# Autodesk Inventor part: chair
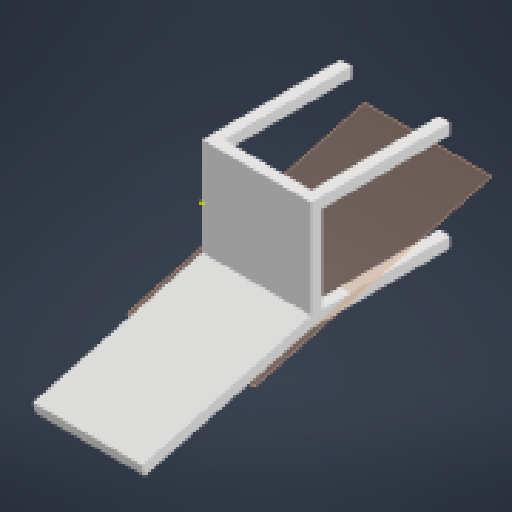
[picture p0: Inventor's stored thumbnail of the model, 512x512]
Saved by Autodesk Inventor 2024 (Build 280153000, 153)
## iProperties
Created: 2023-09
Part Number: chair
Material: Generic
Document SubType Name: Modeling
Designer: mammothbane
Density: 1 g/cm^3
Appearance: Default
Author: mammothbane
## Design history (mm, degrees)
sketch "sk_chair_base"
  geometry: L1 (-250, 250)-(250, 250); L2 (250, 250)-(250, -250); L3 (250, -250)-(-250, -250); L4 (-250, -250)-(-250, 250); L5 (-250, 250)-(250, -250); L6 (250, 250)-(-250, -250); 1 further point
  constraints: 12 end point, 2 midpoint, 2 parallel, 1 horizontal, 1 perpendicular
  dimensions: "base_width" = 500 distance of L2.end L3.end; "base_depth" = 500 distance of L1.end L2.end
extrude "chair_base" new body sketch "sk_chair_base" taper "base_draft" = 0 deg; distance "base_thickness" = 50.8
sketch "sk_leg_profile"
  geometry: L1 (250, 250)-(-250, 250) reference; L2 (-250, 250)-(-200, 250); L3 (-200, 250)-(-200, 200); L4 (-200, 200)-(-250, 200); L5 (-250, 200)-(-250, 250); 2 further points
  constraints: 8 end point, 2 parallel, 1 horizontal, 1 perpendicular
  dimensions: "leg_width" = 50 distance of L3.end L4.end; "leg_depth" = 50 distance of L2.end L3.end (= leg_width)
extrude "chair_leg" join sketch "sk_leg_profile" taper "leg_draft" = 0 deg; distance "leg_height" = 635
mirror "mirror_leg"
mirror "mirror_leg2"
node "pl_chair_back"
sketch "sk_back_profile"
  geometry: L1 (0, 0)-(500, 0) reference; L2 (500, 0)-(0, 0); L3 (0, 0)-(0, -788.88); L4 (0, -788.88)-(500, -788.88); L5 (500, -788.88)-(500, 0); L6 (0, 129.41)-(0, 0) reference; L7 (500, 0)-(0, 0); L8 (0, 0)-(0, 50.8); L9 (0, 50.8)-(500, 50.8); L10 (500, 50.8)-(500, 0); 2 further points
  constraints: 16 end point, 4 parallel, 2 horizontal, 2 perpendicular, 1 collinear, 1 midpoint, 1 point on line
  dimensions: "back_height_full" = 788.88045 distance from line of L1 point (250, -788.88) (computed from back_height, back_angle); "back_overflow" = 50.8 distance between parallel lines of L9 L1 (= base_thickness)
extrude "chair_back" join sketch "sk_back_profile" taper "back_draft" = 0 deg; distance "back_thickness" = 50.8 (= base_thickness)
sketch "Sketch4"
  geometry: 1 further point
node "sld_chair"
other parameters: "back_angle_full" = 195 deg (computed from back_angle), "back_angle" = 15 deg [user parameter; used in 2 equation terms], "back_height" = 762 [user parameter; used in 1 equation term]
